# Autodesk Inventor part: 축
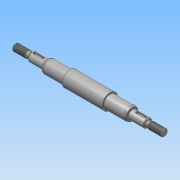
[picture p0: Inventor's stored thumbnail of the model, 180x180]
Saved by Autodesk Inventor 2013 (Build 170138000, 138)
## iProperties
Created: 2015-11
Part Number: 축
Material: 강철, 연강
Document SubType Name: 판금
Designer: mduedu
Density: 1 g/cm^3
Sheet Metal Rule: 기본값
Author: mduedu
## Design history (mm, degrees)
sketch "스케치1"
  geometry: L1 (-86, 0)-(86, 0); L2 (-86, 0)-(-86, 4); L3 (-86, 4)-(-70.732, 4); L4 (-70.732, 4)-(-69, 3); L5 (-69, 3)-(-67, 3); L6 (-67, 3)-(-67, 5); L7 (-67, 5)-(-49, 5); L8 (-49, 5)-(-49, 6.55); L9 (-47.355, 7.5)-(-23, 7.5); L10 (-23, 7.5)-(-23, 9); L11 (0, 0)-(0, 9); L12 (86, 4)-(70.732, 4); L13 (70.732, 4)-(69, 3); L14 (69, 3)-(67, 3); L15 (67, 3)-(67, 5); L16 (67, 5)-(49, 5); L17 (23, 7.5)-(23, 9); L18 (86, 0)-(86, 4); L19 (-23, 9)-(23, 9); L20 (-49, 6.55)-(-47.355, 7.5); L21 (47.355, 7.5)-(23, 7.5); L22 (49, 6.55)-(47.355, 7.5); L23 (49, 5)-(49, 6.55); 1 further point
  constraints: 46 end point, 10 symmetric about line, 6 perpendicular, 5 parallel, 2 midpoint, 1 coincident, 1 horizontal
  dimensions: "d0" = 172 distance of L1.start L1.end (derived); "d1" = 8 diameter of L3 L1; "d2" = 30 deg angle of L4 L5; "d3" = 6 diameter of L5 L1; "d4" = 10 diameter of L7 L1; "d5" = 15 diameter of L9 L1; "d6" = 18 diameter of L19 L1; "d8" = 18 distance of L6.end L7.end; "d9" = 46 distance of L10.end L17.end; "d10" = 2 distance of L4.end L5.end; "d11" = 17 distance from line of L4.end L2; "d16" = 13.1 diameter of L8.end L1; "d17" = 30 deg angle of L20 L9; "d18" = 26 distance between parallel lines of L10 L8
revolve "회전1" sketch "스케치1" stored, may be unused: angle "d12" = 90 deg
chamfer "모따기1" distance "d13" = 1; stored, may be unused: second distance "d14" = 2, angle "d15" = 45 deg
fillet "모깎기1" dims "d19" = 4, "d20" = 0.5
node "작업 평면1"
sketch "스케치2" dims "d23" = 12
  geometry: L1 (-5.5, 1.5)-(3.5, 1.5); L2 (3.5, 1.5)-(3.5, -1.5); L3 (3.5, -1.5)-(-5.5, -1.5); L4 (-5.5, -1.5)-(-5.5, 1.5); L5 (-9, -4)-(-9, 4) reference; 3 further points
  constraints: 8 end point, 2 midpoint, 2 parallel, 2 vertical alignment, 1 horizontal, 1 perpendicular, 4 other
  dimensions: "d21" = 3 distance between parallel lines of L3 L1; "d24" = 2 dimension on L5
extrude "돌출1" cut sketch "스케치2" distance "d25" = 1.8; taper "d26" = 0 deg
feature "스레드1" dims "d27" = 10, "d28" = 0
feature "스레드2" dims "d29" = 10, "d30" = 0
chamfer "모따기2" distance "d31" = 1; stored, may be unused: second distance "d32" = 2, angle "d33" = 45 deg
fillet "모깎기2" dims "d34" = 0.3
node "솔리드1"
mirror "대칭1"
other parameters: "K계수" = 4.4, "BendRadius" = 0.5 (derived), "BendReliefWidth" = 0.5 (derived), "BendReliefDepth" = 0.25 (derived), "CornerReliefSize" = 2 (derived), "SeamGap" = 0.01, "MinimumRemnant" = 1 (derived), "TransitionRadius" = 0.5 (= BendRadius)
